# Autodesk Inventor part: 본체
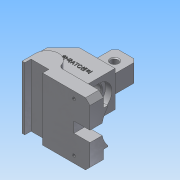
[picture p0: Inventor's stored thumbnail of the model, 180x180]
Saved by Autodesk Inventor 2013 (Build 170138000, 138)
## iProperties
Created: 2016-11
Part Number: 본체
Material: 알루미늄 6061
Document SubType Name: Modeling
Designer: Administrator
Density: 2.71 g/cm^3
Mass: 462.906 g
Surface Area: 317.29 cm^2
Volume: 170.814 cm^3
Author: Administrator
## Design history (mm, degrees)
sketch "스케치1"
  geometry: L1 (-40.5, 0)-(-22.5, 18); L2 (-22.5, 18)-(17.5, 18); L3 (17.5, 18)-(17.5, -22); L4 (49.5, -30)-(-40.5, -30); L5 (-40.5, -30)-(-40.5, 0); L6 (49.5, -30)-(49.5, -22); L7 (49.5, -22)-(17.5, -22); 1 further point
  constraints: 14 end point, 4 perpendicular, 1 horizontal, 1 parallel
  dimensions: "d0" = 58 distance between parallel lines of L3 L5; "d2" = 48 distance between parallel lines of L4 L2; "d3" = 30 distance from line of L4 point (0, 0); "d4" = 17.5 distance from line of point (0, 0) L3; "d5" = 45 deg angle of L2 L1; "d6" = 18 horizontal distance of L1.start L1.end; "d28" = 90 distance of L4.start L4.end; "d30" = 40 distance between parallel lines of L7 L2
extrude "돌출1" new body sketch "스케치1" stored distance "d7" = 40; taper "d8" = 0 deg
sketch "스케치2"
  geometry: 2 further points
  constraints: 1 coincident
hole "구멍1" sketch "스케치2" at (20, 30) diameter "d10" = 20; stored, may be unused: countersink angle "d14" = 90 deg, drill point angle "d16" = 0 deg; dims "d11" = 6, "d12" = 29, "d13" = 7, "d15" = 8
sketch "스케치3"
  geometry: L1 (-26.5, -27)-(-26.5, -42); L2 (-26.5, -42)-(-23.5, -42); L3 (-23.5, -42)-(-23.5, -35); L4 (-23.5, -35)-(-3.5, -35); L5 (-3.5, -35)-(-3.5, -42); L6 (-3.5, -42)-(49.5, -42); L7 (49.5, -42)-(49.5, -27); L8 (49.5, -27)-(-0.5, -27); L9 (49.5, -22)-(49.5, -30) reference; A1 r 13 centre (-13.5, -27) between (-0.5, -27) and (-26.5, -27); 1 further point
  constraints: 16 end point, 3 collinear, 3 parallel, 3 perpendicular, 2 point on circle, 1 centre point, 1 horizontal alignment, 1 tangent, 1 vertical
  dimensions: "d17" = 26 diameter of A1; "d18" = 15 distance of L6.end L7.end; "d19" = 42 distance from line of L6 point (0, 0); "d20" = 20 distance between parallel lines of L5 L3; "d21" = 7 distance between parallel lines of L2 L4; "d22" = 3 distance of L1.end L2.end; "d25" = 63 distance from line of L7 A1.centre
extrude "돌출2" join sketch "스케치3" stored distance "d26" = 70; taper "d27" = 0 deg
sketch "스케치4"
  geometry: L1 (-15, -20)-(55, -20) reference; L2 (14, -6.373)-(14, -20); L3 (26, -6.373)-(26, -20); L4 (14, -20)-(26, -20); A1 r 29 centre (20, 22) between (26, -6.373) and (14, -6.373); 2 further points
  constraints: 6 end point, 2 perpendicular, 2 point on circle, 2 point on line, 1 centre point, 1 coincident, 1 collinear, 1 midpoint, 1 vertical alignment
  dimensions: "d31" = 58 diameter of A1; "d32" = 12 distance between parallel lines of L3 L2
extrude "돌출3" cut sketch "스케치4" distance "d33" = 18; taper "d34" = 0 deg
sketch "스케치5"
  geometry: L1 (-12.5, 48)-(12.5, 48); L2 (12.5, 48)-(12.5, 18); L3 (12.5, 18)-(-12.5, 18); L4 (-12.5, 18)-(-12.5, 48); L5 (-22.5, 18)-(17.5, 18) reference; L6 (49.5, -42)-(-3.5, -42) reference; 2 further points
  constraints: 8 end point, 2 parallel, 1 collinear, 1 horizontal, 1 midpoint, 1 perpendicular, 1 vertical alignment
  dimensions: "d35" = 25 distance of L1.start L1.end; "d37" = 90 distance between parallel lines of L6 L1
extrude "돌출4" join sketch "스케치5" stored distance "d38" = 20; taper "d39" = 0 deg
sketch "스케치6"
  geometry: C1 r 4 at (0, 35); 1 further point
  constraints: 1 centre point, 1 vertical alignment
  dimensions: "d40" = 8 diameter of C1; "d42" = 35 distance of point (0, 0) C1.centre
extrude "돌출5" cut sketch "스케치6" stored distance "d43" = 20; taper "d44" = 0 deg
chamfer "모따기1" distance "d45" = 4; stored, may be unused: second distance "d46" = 2, angle "d47" = 45 deg
chamfer "모따기2" distance "d48" = 5; stored, may be unused: second distance "d49" = 2, angle "d50" = 45 deg
chamfer "모따기3" distance "d51" = 1; stored, may be unused: second distance "d52" = 2, angle "d53" = 45 deg
fillet "모깎기1" dims "d54" = 3, "d55" = 5
sketch "스케치7"
  geometry: L1 (0, 0)-(0, 10) reference; 2 further points
  dimensions: "d56" = 18 distance from line of L1 point (-18, 2.5); "d57" = 27.5 vertical distance of point (-49.5, 30) point (-18, 2.5)
hole "구멍2" sketch "스케치7" at (-18, 2.5) diameter "d58" = 3.242; stored, may be unused: countersink angle "d62" = 90 deg, drill point angle "d64" = 0 deg; dims "d59" = 15, "d60" = 29, "d61" = 7, "d63" = 15
sketch "스케치8"
  geometry: L1 (17.5, 18)-(-22.5, 18) reference; 2 further points
  constraints: 1 other
  dimensions: "d65" = 18 distance from line of L1 point (-7.5, 0); "d66" = 25 horizontal distance of L1.start point (-7.5, 0)
feature "엠보싱1" sketch "스케치8" dims "d2" = 48, "d17" = 26, "d18" = 15, "d19" = 42, "d20" = 20, "d21" = 7, "d22" = 3, "d25" = 63, "d67" = 0.5, "d68" = 0
node "솔리드1"
mirror "대칭1"
